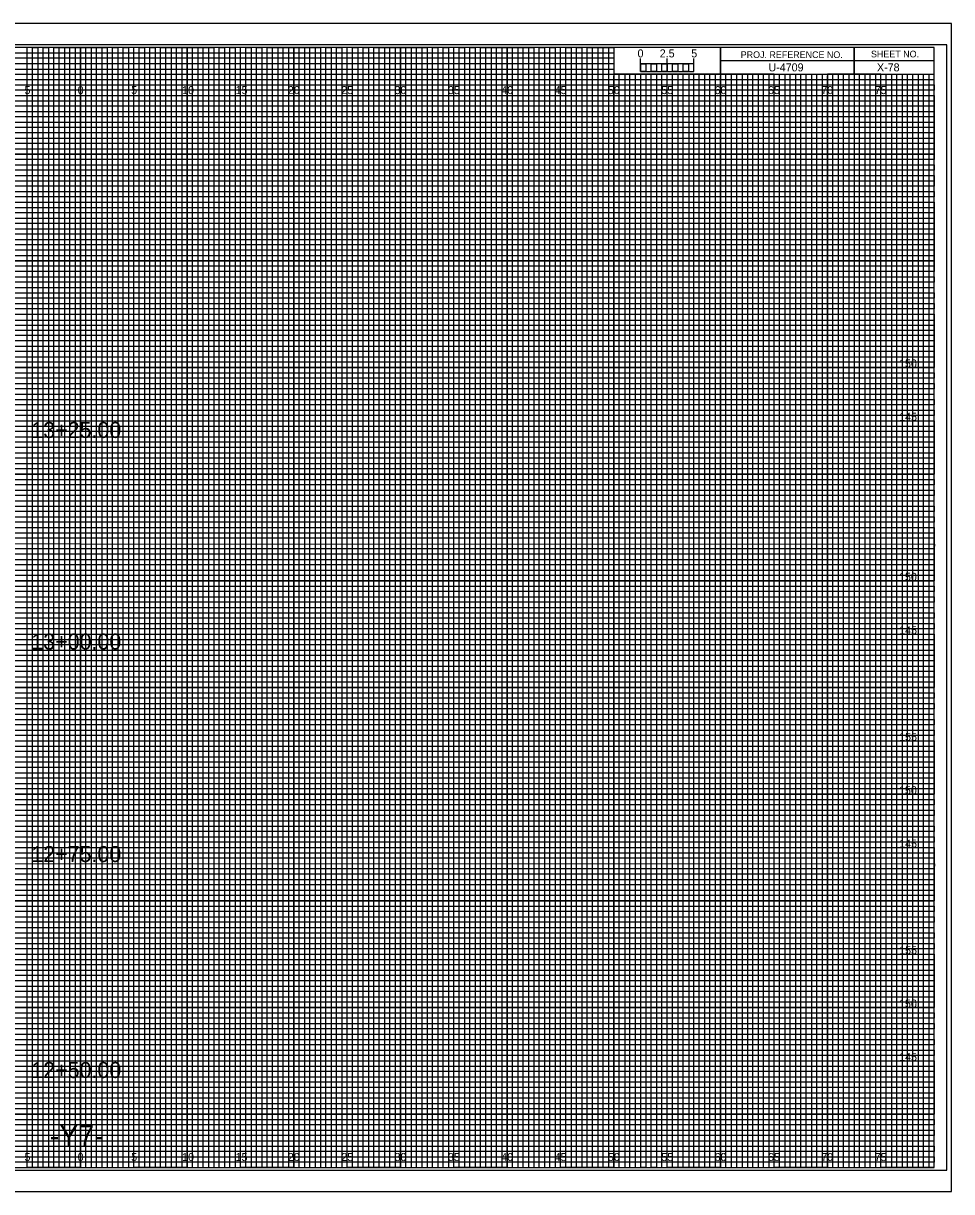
# Model space of a CAD drawing. Extents: x -7 to 162, y 218 to 327.
# Drawn here: x 74.6 to 161.7, y 217.7 to 327.2 of the extents above; entities that cross this region are included whole.
import ezdxf

# ---------------------------------------------------------------- set-up
doc = ezdxf.new("R2010")
doc.units = 0
for name, color, linetype in [('Prop CMT Conc Surface', 7, 'Continuous'), ('Prop CMT Concrete Structures', 7, 'Continuous'), ('Prop CMT Pvmt Course 1', 7, 'Continuous'), ('Prop CMT Pvmt Course 1 CG', 7, 'Continuous'), ('Prop CMT Pvmt Surface Shoulder', 7, 'Continuous'), ('Prop CMT Pvmt Wedge Surface 1', 7, 'Continuous'), ('Prop CMT Pvmt Wedge Surface 2', 7, 'Continuous'), ('Prop CMT Pvmt Wedge Surface 3', 7, 'Continuous'), ('Prop XS Alignment Label', 7, 'Continuous'), ('Prop XS Bar Scale Labels', 7, 'Continuous'), ('Prop XS Ditch Standard Text', 7, 'Continuous'), ('Prop XS Earthwork Shape', 7, 'Continuous'), ('Prop XS Hydro Elevations', 7, 'Continuous'), ('Prop XS Project Number', 7, 'Continuous'), ('Prop XS SE Text', 7, 'Continuous'), ('Prop XS Sheet Number', 7, 'Continuous'), ('Prop XS Side Slope Text', 7, 'Continuous')]:
    doc.layers.add(name, color=color, linetype=linetype)

msp = doc.modelspace()

# ---------------------------------------------------------------- linework, layer by layer
at = {"layer": 'Prop CMT Conc Surface'}
for p, q in [((133.5, 322.5), (133, 322.5)), ((133, 322.5), (133, 220)), ((133.5, 220), (133.5, 322.5)), ((134.5, 322.5), (134, 322.5)), ((134, 322.5), (134, 220)), ((134.5, 220), (134.5, 322.5)), ((133, 220), (132.5, 220)), ((134, 220), (133.5, 220))]:
    msp.add_line(p, q, dxfattribs=at)
for points in [[(75, 220), (75.5, 220), (75.5, 325), (76, 325), (76, 220)], [(76, 220), (76.5, 220), (76.5, 325), (77, 325), (77, 220)], [(77.5, 220), (78, 220), (78, 325), (78.5, 325), (78.5, 220)], [(78.5, 220), (79, 220), (79, 325), (79.5, 325), (79.5, 220)], [(80, 220), (80.5, 220), (80.5, 325), (81, 325), (81, 220)], [(81, 220), (81.5, 220), (81.5, 325), (82, 325), (82, 220)], [(82.5, 220), (83, 220), (83, 325), (83.5, 325), (83.5, 220)], [(83.5, 220), (84, 220), (84, 325), (84.5, 325), (84.5, 220)], [(85, 220), (85.5, 220), (85.5, 325), (86, 325), (86, 220)], [(86, 220), (86.5, 220), (86.5, 325), (87, 325), (87, 220)], [(87.5, 220), (88, 220), (88, 325), (88.5, 325), (88.5, 220)], [(88.5, 220), (89, 220), (89, 325), (89.5, 325), (89.5, 220)], [(90, 220), (90.5, 220), (90.5, 325), (91, 325), (91, 220)], [(91, 220), (91.5, 220), (91.5, 325), (92, 325), (92, 220)], [(92.5, 220), (93, 220), (93, 325), (93.5, 325), (93.5, 220)], [(93.5, 220), (94, 220), (94, 325), (94.5, 325), (94.5, 220)], [(95, 220), (95.5, 220), (95.5, 325), (96, 325), (96, 220)], [(96, 220), (96.5, 220), (96.5, 325), (97, 325), (97, 220)], [(97.5, 220), (98, 220), (98, 325), (98.5, 325), (98.5, 220)], [(98.5, 220), (99, 220), (99, 325), (99.5, 325), (99.5, 220)], [(100, 220), (100.5, 220), (100.5, 325), (101, 325), (101, 220)], [(101, 220), (101.5, 220), (101.5, 325), (102, 325), (102, 220)], [(102.5, 220), (103, 220), (103, 325), (103.5, 325), (103.5, 220)], [(103.5, 220), (104, 220), (104, 325), (104.5, 325), (104.5, 220)], [(105, 220), (105.5, 220), (105.5, 325), (106, 325), (106, 220)], [(106, 220), (106.5, 220), (106.5, 325), (107, 325), (107, 220)], [(107.5, 220), (108, 220), (108, 325), (108.5, 325), (108.5, 220)], [(108.5, 220), (109, 220), (109, 325), (109.5, 325), (109.5, 220)], [(110, 220), (110.5, 220), (110.5, 325), (111, 325), (111, 220)], [(111, 220), (111.5, 220), (111.5, 325), (112, 325), (112, 220)], [(112.5, 220), (113, 220), (113, 325), (113.5, 325), (113.5, 220)], [(113.5, 220), (114, 220), (114, 325), (114.5, 325), (114.5, 220)], [(115, 220), (115.5, 220), (115.5, 325), (116, 325), (116, 220)], [(116, 220), (116.5, 220), (116.5, 325), (117, 325), (117, 220)], [(117.5, 220), (118, 220), (118, 325), (118.5, 325), (118.5, 220)], [(118.5, 220), (119, 220), (119, 325), (119.5, 325), (119.5, 220)], [(120, 220), (120.5, 220), (120.5, 325), (121, 325), (121, 220)], [(121, 220), (121.5, 220), (121.5, 325), (122, 325), (122, 220)], [(122.5, 220), (123, 220), (123, 325), (123.5, 325), (123.5, 220)], [(123.5, 220), (124, 220), (124, 325), (124.5, 325), (124.5, 220)], [(125, 220), (125.5, 220), (125.5, 325), (126, 325), (126, 220)], [(126, 220), (126.5, 220), (126.5, 325), (127, 325), (127, 220)], [(127.5, 220), (128, 220), (128, 325), (128.5, 325), (128.5, 220)], [(128.5, 220), (129, 220), (129, 325), (129.5, 325), (129.5, 220)], [(130, 220), (130.5, 220), (130.5, 322.5), (131.01, 322.5), (131.01, 220)], [(131, 220), (131.5, 220), (131.5, 322.5), (132, 322.5), (132, 220)], [(135, 220), (135.49, 220), (135.49, 322.5), (136, 322.5), (136, 220)], [(136, 220), (136.5, 220), (136.5, 322.5), (137.03, 322.5), (137.03, 220)], [(137.5, 220), (138, 220), (138, 322.5), (138.5, 322.5), (138.5, 220)], [(138.5, 220), (139, 220), (139, 322.5), (139.5, 322.5), (139.5, 220)], [(140, 220), (140.5, 220), (140.5, 322.5), (141, 322.5), (141, 220)], [(141, 220), (141.5, 220), (141.5, 322.5), (142, 322.5), (142, 220)], [(142.5, 220), (143, 220), (143, 322.5), (143.5, 322.5), (143.5, 220)], [(143.5, 220), (144, 220), (144, 322.5), (144.5, 322.5), (144.5, 220)], [(145, 220), (145.5, 220), (145.5, 322.5), (146, 322.5), (146, 220)], [(146, 220), (146.5, 220), (146.5, 322.5), (147, 322.5), (147, 220)], [(147.5, 220), (148, 220), (148, 322.5), (148.5, 322.5), (148.5, 220)], [(148.5, 220), (149, 220), (149, 322.5), (149.5, 322.5), (149.5, 220)], [(150, 220), (150.5, 220), (150.5, 322.5), (151, 322.5), (151, 220)], [(151, 220), (151.5, 220), (151.5, 322.5), (152, 322.5), (152, 220)], [(152.5, 220), (153, 220), (153, 322.5), (153.5, 322.5), (153.5, 220)], [(153.5, 220), (154, 220), (154, 322.5), (154.5, 322.5), (154.5, 220)], [(155, 220), (155.5, 220), (155.5, 322.5), (156, 322.5), (156, 220)], [(156, 220), (156.5, 220), (156.5, 322.5), (157, 322.5), (157, 220)], [(157.5, 220), (158, 220), (158, 322.5), (158.5, 322.5), (158.5, 220)], [(158.5, 220), (159, 220), (159, 322.5), (159.5, 322.5), (159.5, 220)]]:
    msp.add_lwpolyline(points, dxfattribs=at)
at = {"layer": 'Prop CMT Concrete Structures'}
for p, q in [((132.5, 322.75), (132.5, 323.95)), ((132.5, 323.45), (132.5, 323.95)), ((135, 322.75), (135, 323.95)), ((137.5, 322.75), (137.5, 323.95)), ((137.5, 323.45), (137.5, 323.95))]:
    msp.add_line(p, q, dxfattribs=at)
for points in [[(137.5, 323.45), (132.5, 323.45), (132.5, 322.75), (137.5, 322.75)], [(132.5, 323.45), (133, 323.45), (133, 322.75), (132.5, 322.75)], [(133.5, 323.45), (134, 323.45), (134, 322.75), (133.5, 322.75)], [(134.5, 323.45), (135, 323.45), (135, 322.75), (134.5, 322.75)], [(135.5, 323.45), (136, 323.45), (136, 322.75), (135.5, 322.75)], [(136.5, 323.45), (137, 323.45), (137, 322.75), (136.5, 322.75)]]:
    msp.add_lwpolyline(points, close=True, dxfattribs=at)
at = {"layer": 'Prop CMT Pvmt Course 1'}
for p, q in [((152.5, 325), (152.5, 322.5)), ((152.5, 322.5), (152.5, 325)), ((160, 323.75), (140, 323.75)), ((140, 323.75), (140, 322.5)), ((140, 322.5), (160, 322.5))]:
    msp.add_line(p, q, dxfattribs=at)
for points in [[(160, 325), (0, 325), (0, 220), (160, 220)], [(140, 325), (130, 325), (130, 322.51), (140, 322.51)], [(160, 325), (140, 325), (140, 322.5), (160, 322.5)]]:
    msp.add_lwpolyline(points, close=True, dxfattribs=at)
at = {"layer": 'Prop CMT Pvmt Course 1 CG'}
msp.add_lwpolyline([(-6.7, 217.75), (161.65, 217.75), (161.65, 327.25), (-6.7, 327.25)], close=True, dxfattribs=at)
at = {"layer": 'Prop CMT Pvmt Surface Shoulder'}
for p, q in [((0, 324.5), (130, 324.5)), ((130, 324.5), (130, 323.99)), ((130, 323.99), (0, 323.99)), ((0, 323.5), (130, 323.5)), ((130, 323.5), (130, 322.94)), ((130, 322.94), (0, 322.94)), ((0, 322), (160, 322))]:
    msp.add_line(p, q, dxfattribs=at)
for points in [[(0, 321.5), (135, 321.5), (160, 321.5), (160, 321), (0, 321)], [(0, 320.5), (160, 320.5), (160, 319.5), (0, 319.5)], [(0, 319), (160, 319), (160, 318.5), (0, 318.49)], [(0, 318), (160, 318), (160, 317), (0, 317)], [(0, 316.5), (160, 316.5), (160, 316), (0, 316)], [(0, 315.5), (160, 315.5), (160, 314.5), (0, 314.5)], [(0, 314), (160, 314), (160, 313.5), (0, 313.5)], [(0, 313), (160, 313), (160, 312), (0, 312)], [(0, 311.5), (160, 311.5), (160, 311), (0, 311)], [(0, 310.5), (160, 310.5), (160, 309.5), (0, 309.5)], [(0, 309), (160, 309), (160, 308.5), (0, 308.5)], [(0, 308), (160, 308), (160, 306.98), (160, 306.5), (160, 306), (0, 306)], [(0, 307), (160, 307), (160, 306.5), (0, 306.5)], [(0, 305.5), (160, 305.5), (160, 304.5), (0, 304.51)], [(0, 304.51), (160, 304.5), (160, 304), (0, 304)], [(0, 303.5), (160, 303.5), (160, 303), (0, 303)], [(0, 302), (160, 302), (160, 301.5), (0, 301.5)], [(0, 301), (160, 301), (160, 300.5), (0, 300.5)], [(-0.04, 299.44), (160, 299.44), (160, 298.94), (-0.04, 298.94)], [(0, 298.5), (160, 298.5), (160, 298), (0, 298)], [(0, 297), (160, 297), (160, 296.5), (0, 296.5)], [(0, 296), (160, 296), (160, 295.5), (0, 295.5)], [(0, 294.5), (160, 294.5), (160, 294), (0, 294)], [(0, 293.5), (160, 293.5), (160, 293), (0, 293)], [(0, 292), (160, 292), (160, 291.5), (0, 291.5)], [(0, 291), (160, 291), (160, 290.5), (0, 290.5)], [(0, 289.5), (160, 289.5), (160, 288.99), (0, 289)], [(0, 288.5), (160, 288.5), (160, 288), (0, 288)], [(0, 287), (160, 287), (160, 286.5), (0, 286.5)], [(0, 286), (160, 286), (160, 285.5), (0, 285.5)], [(0, 284.5), (160, 284.5), (160, 284), (0, 284)], [(0, 283.5), (160, 283.5), (160, 283), (0, 283)], [(0, 282), (160, 282), (160, 281.5), (0, 281.5)], [(0, 281), (160, 281), (160, 280.5), (0, 280.5)], [(0, 279.5), (160, 279.5), (160, 279), (0, 279)], [(0, 278.5), (160.03, 278.45), (160, 278), (0, 278)], [(0, 277), (160, 277), (160, 276.5), (0, 276.5)], [(0, 276), (160, 276), (160, 275.5), (0, 275.5)], [(0, 274.5), (160, 274.5), (160, 274), (0, 274)], [(0, 273.5), (160, 273.5), (160, 273), (0, 273)], [(0, 272), (160, 272), (160, 271.5), (0, 271.5)], [(0, 271), (160, 271), (160, 270.5), (0, 270.5)], [(0, 269.5), (160, 269.5), (160, 269), (0, 269)], [(0, 268.5), (160, 268.5), (160, 268), (0, 268)], [(0, 267), (160, 267), (160, 266.5), (0, 266.5)], [(0, 266), (160, 266), (160, 265.5), (0, 265.5)], [(0, 264.5), (160, 264.5), (160, 264), (0, 264)], [(0, 263.5), (160, 263.5), (160, 263), (0, 263)], [(0, 262), (160, 262), (160, 261.5), (0, 261.5)], [(0, 261), (160, 261), (160, 260.5), (0, 260.5)], [(0, 259.5), (160, 259.5), (160, 258.99), (0, 259)], [(0, 258.5), (160, 258.5), (160, 258), (0, 258)], [(0, 257), (160, 257), (160, 256.5), (0, 256.5)], [(0, 256), (160, 256), (160, 255.5), (0, 255.5)], [(0, 254.5), (160, 254.5), (160, 254), (0, 254)], [(0, 253.5), (160, 253.5), (160, 253), (0, 253)], [(0, 252), (160, 252), (160, 251.5), (0, 251.5)], [(0, 251), (160, 251), (160, 250.5), (0, 250.5)], [(0, 249.5), (160, 249.5), (160, 249), (0, 249)], [(0, 248.5), (160.03, 248.46), (160, 248), (0, 248)], [(0, 247), (160, 247), (160, 246.5), (0, 246.5)], [(0, 246), (160, 246), (160, 245.5), (0, 245.5)], [(0, 244.5), (160, 244.5), (160, 244), (0, 244)], [(0, 243.5), (160, 243.5), (160, 243), (0, 243)], [(0, 242), (160, 242), (160, 241.5), (0, 241.5)], [(0, 241), (160, 241), (160, 240.5), (0, 240.5)], [(0, 239.5), (160, 239.5), (160, 239), (0, 239)], [(0, 238.5), (160, 238.5), (160, 238), (0, 238)], [(0, 237), (160, 237), (160, 236.5), (0, 236.5)], [(0, 236), (160, 236), (160, 235.5), (0, 235.5)], [(0, 234.5), (160, 234.5), (160, 234), (0, 234)], [(0, 233.5), (160, 233.5), (160, 233), (0, 233)], [(0, 232), (160, 232), (160, 231.5), (0, 231.5)], [(0, 231), (160, 231), (160, 230.5), (0, 230.5)], [(0, 229.5), (160, 229.5), (160, 229), (0, 229)], [(0, 228.5), (160, 228.5), (160, 228), (0, 228)], [(0, 227), (160, 227), (160, 226.5), (0, 226.5)], [(0, 226), (160, 226), (160, 225.5), (0, 225.5)], [(0, 224.5), (160, 224.5), (160, 224), (0, 224)], [(0, 223.5), (160, 223.5), (160, 223), (0, 223)], [(0, 222), (160, 222), (160, 221.5), (0, 221.5)], [(0, 221), (160, 221), (160, 220.5), (0, 220.5)]]:
    msp.add_lwpolyline(points, dxfattribs=at)
at = {"layer": 'Prop CMT Pvmt Wedge Surface 2'}
for p, q in [((75, 325), (70, 325)), ((75, 220), (75, 325)), ((85, 325), (80, 325)), ((80, 325), (80, 220)), ((85, 220), (85, 325)), ((95, 325), (90, 325)), ((90, 325), (90, 220)), ((95, 220), (95, 325)), ((105, 325), (100, 325)), ((100, 325), (100, 220)), ((105, 220), (105, 325)), ((115, 325), (110, 325)), ((110, 325), (110, 220)), ((115, 220), (115, 325)), ((125, 325), (120, 325)), ((120, 325), (120, 220)), ((125, 220), (125, 325)), ((130, 325), (130, 220)), ((135, 220), (135, 322.5)), ((145, 322.5), (140, 322.5)), ((140, 322.5), (140, 220)), ((145, 220), (145, 322.5)), ((155, 322.5), (150, 322.5)), ((150, 322.5), (150, 220)), ((155, 220), (155, 322.5)), ((80, 220), (75, 220)), ((90, 220), (85, 220)), ((100, 220), (95, 220)), ((110, 220), (105, 220)), ((120, 220), (115, 220)), ((130, 220), (125, 220)), ((140, 220), (135, 220)), ((150, 220), (145, 220)), ((160, 220), (155, 220)), ((160, 220), (160, 220))]:
    msp.add_line(p, q, dxfattribs=at)
for points in [[(0, 320), (160, 320), (160, 315), (0, 315)], [(0, 310), (160, 310), (160, 305), (0, 305)], [(0, 300), (160, 300), (160, 295), (0, 295)], [(0, 290), (160, 290), (160, 285), (0, 285)], [(0, 280), (160, 280), (160, 275), (0, 275)], [(0, 270), (160, 270), (160, 265), (0, 265)], [(0, 260), (160, 260), (160, 255), (0, 255)], [(0, 250), (160, 250), (160, 245), (0, 245)], [(0, 240), (160, 240), (160, 235), (0, 235)], [(0, 230), (160, 230), (160, 225), (0, 225)]]:
    msp.add_lwpolyline(points, dxfattribs=at)
at = {"layer": 'Prop CMT Pvmt Wedge Surface 3'}
for points in [[(72.5, 220), (77.5, 220), (77.5, 325), (82.5, 325), (82.5, 220), (87.5, 220), (87.5, 325), (92.5, 325), (92.5, 220), (97.5, 220), (97.5, 325), (102.5, 325), (102.5, 220), (107.5, 220), (107.5, 325), (112.5, 325), (112.5, 220), (117.5, 220), (117.5, 325), (122.5, 325), (122.5, 220), (127.5, 220), (127.5, 325), (129.97, 325), (130, 325), (130, 322.5), (132.5, 322.5), (132.5, 220), (137.5, 220), (137.5, 322.5), (142.5, 322.5), (142.5, 220), (147.5, 220), (147.5, 322.5), (152.5, 322.5), (152.5, 220), (157.5, 220), (157.5, 322.5)], [(0, 322.5), (137.5, 322.5)], [(0, 312.5), (160, 312.5), (160, 317.5), (0, 317.5)], [(0, 302.5), (160, 302.5), (160, 307.5), (0, 307.5)], [(0, 292.5), (160, 292.5), (160, 297.5), (0, 297.5)], [(0, 282.5), (160, 282.5), (160, 287.5), (0, 287.5)], [(0, 272.5), (160, 272.5), (160, 277.5), (0, 277.5)], [(0, 262.5), (160, 262.5), (160, 267.5), (0, 267.5)], [(0, 252.5), (160, 252.5), (160, 257.5), (0, 257.5)], [(0, 242.5), (160, 242.5), (160, 247.5), (0, 247.5)], [(0, 232.5), (160, 232.5), (160, 237.5), (0, 237.5)], [(0, 222.5), (160, 222.5), (160, 227.5), (0, 227.5)]]:
    msp.add_lwpolyline(points, dxfattribs=at)
at = {"layer": 'Prop XS Ditch Standard Text'}
for p, q in [((161.65, 327.25), (-6.7, 327.25)), ((-6.7, 217.75), (161.65, 217.75))]:
    msp.add_line(p, q, dxfattribs=at)
at = {"layer": 'Prop XS SE Text'}
for p, q in [((75, 220), (75, 325)), ((80, 220), (80, 325)), ((85, 220), (85, 325)), ((90, 220), (90, 325)), ((95, 220), (95, 325)), ((100, 220), (100, 325)), ((105, 220), (105, 325)), ((110, 220), (110, 325)), ((115, 220), (115, 325)), ((120, 220), (120, 325)), ((125, 220), (125, 325)), ((130, 220), (130, 322.34)), ((135, 220), (135, 322.34)), ((140, 220), (140, 322.34)), ((145, 220), (145, 322.34)), ((150, 220), (150, 322.34)), ((155, 220), (155, 322.34)), ((0, 320), (160, 320)), ((0, 315), (160, 315)), ((0, 310), (160, 310)), ((0, 305), (160, 305)), ((0, 300), (160, 300)), ((0, 295), (160, 295)), ((0, 290), (160, 290)), ((0, 285), (160, 285)), ((0, 280), (160, 280)), ((0, 275), (160, 275)), ((0, 270), (160, 270)), ((0, 265), (160, 265)), ((0, 260), (160, 260)), ((0, 255), (160, 255)), ((0, 250), (160, 250)), ((0, 245), (160, 245)), ((0, 240), (160, 240)), ((0, 235), (160, 235)), ((0, 230), (160, 230)), ((0, 225), (160, 225))]:
    msp.add_line(p, q, dxfattribs=at)
at = {"layer": 'Prop XS Side Slope Text'}
msp.add_lwpolyline([(-5.4, 219.75), (161.2, 219.75), (161.2, 325.25), (-5.4, 325.25)], close=True, dxfattribs=at)

# ---------------------------------------------------------------- texts
at = {"layer": 'Prop CMT Concrete Structures'}
msp.add_text('0', height=0.75, dxfattribs=at).set_placement((132.21, 324.06))
at = {"layer": 'Prop CMT Pvmt Course 1'}
for s, p in [('PROJ. REFERENCE NO.', (141.88, 324)), ('SHEET NO.', (154.09, 324.06))]:
    msp.add_text(s, height=0.625, dxfattribs=at).set_placement(p)
at = {"layer": 'Prop CMT Pvmt Wedge Surface 1'}
for s, p in [('5', (74.74, 320.62)), ('0', (79.73, 320.62)), ('0', (79.73, 320.62)), ('5', (84.74, 320.62)), ('10', (89.52, 320.62)), ('15', (94.53, 320.62)), ('20', (99.43, 320.62)), ('25', (104.44, 320.62)), ('30', (109.43, 320.62)), ('35', (114.44, 320.62)), ('40', (119.43, 320.62)), ('45', (124.44, 320.62)), ('50', (129.43, 320.62)), ('55', (134.44, 320.62)), ('60', (139.43, 320.62)), ('65', (144.44, 320.62)), ('70', (149.43, 320.62)), ('75', (154.44, 320.62)), ('5', (74.74, 220.62)), ('0', (79.73, 220.62)), ('0', (79.73, 220.62)), ('5', (84.74, 220.62)), ('10', (89.52, 220.62)), ('15', (94.53, 220.62)), ('20', (99.43, 220.62)), ('25', (104.44, 220.62)), ('30', (109.43, 220.62)), ('35', (114.44, 220.62)), ('40', (119.43, 220.62)), ('45', (124.44, 220.62)), ('50', (129.43, 220.62)), ('55', (134.44, 220.62)), ('60', (139.43, 220.62)), ('65', (144.44, 220.62)), ('70', (149.43, 220.62)), ('75', (154.44, 220.62))]:
    msp.add_text(s, height=0.75, dxfattribs=at).set_placement(p)
at = {"layer": 'Prop XS Alignment Label'}
msp.add_text('-Y7-', height=2, dxfattribs=at).set_placement((77.12, 222))
at = {"layer": 'Prop XS Bar Scale Labels'}
for s, p in [('2.5', (134.29, 324.06)), ('5', (137.24, 324.06))]:
    msp.add_text(s, height=0.75, dxfattribs=at).set_placement(p)
at = {"layer": 'Prop XS Earthwork Shape'}
for s, p in [('13+25.00', (75.39, 288.39)), ('13+00.00', (75.39, 268.56)), ('12+75.00', (75.39, 248.64)), ('12+50.00', (75.39, 228.4))]:
    msp.add_text(s, height=1.5, dxfattribs=at).set_placement(p)
at = {"layer": 'Prop XS Hydro Elevations'}
for s, p in [('150', (156.72, 295)), ('145', (156.73, 290)), ('150', (156.72, 275)), ('145', (156.73, 270)), ('155', (156.73, 260)), ('150', (156.72, 255)), ('145', (156.73, 250)), ('155', (156.73, 240)), ('150', (156.72, 235)), ('145', (156.73, 230))]:
    msp.add_text(s, height=0.75, dxfattribs=at).set_placement(p)
at = {"layer": 'Prop XS Project Number'}
msp.add_text('U-4709', height=0.75, dxfattribs=at).set_placement((144.48, 322.75))
at = {"layer": 'Prop XS Sheet Number'}
msp.add_text('X-78', height=0.75, dxfattribs=at).set_placement((154.65, 322.75))

doc.saveas('drawing.dxf')
